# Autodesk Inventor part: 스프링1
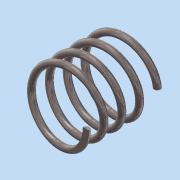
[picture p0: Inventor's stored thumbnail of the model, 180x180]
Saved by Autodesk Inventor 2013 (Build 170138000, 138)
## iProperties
Created: 2016-07
Part Number: 스프링1
Material: 스테인리스강
Document SubType Name: Modeling
Designer: Administrator
Density: 8.08 g/cm^3
Mass: 6.33594 g
Surface Area: 15.8123 cm^2
Volume: 0.784151 cm^3
Author: Administrator
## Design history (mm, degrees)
sketch "스케치1"
  geometry: L1 (0, 0)-(0, 22.5); L2 (0, 22.5)-(11.971, 22.5); C1 r 1 at (10, 0)
  constraints: 4 end point, 1 centre point, 1 horizontal alignment, 1 perpendicular, 1 vertical
  dimensions: "d0" = 22.5 distance of L1.start L1.end (derived); "d1" = 2 diameter of C1; "d2" = 20 diameter of C1.centre L1
feature "코일1" sketch "스케치1" pitch "d3" = 10; turns "d5" = 4; dims "d4" = 22.5 (= d0), "d6" = 0, angle "d7" = 90 deg, angle "d8" = 90 deg, "d9" = 0, "d10" = 0
sketch "스케치2"
  geometry: L1 (25, 15)-(0, 15); L2 (0, 15)-(0, -15); L3 (0, -15)-(25, -15); L4 (25, -15)-(25, 15); 2 further points
  constraints: 8 end point, 2 parallel, 1 coincident, 1 horizontal, 1 midpoint, 1 perpendicular
  dimensions: "d11" = 30 distance between parallel lines of L3 L1; "d13" = 25 distance of L1.start L1.end (derived)
extrude "돌출1" sketch "스케치2" stored distance "d14" = 30; taper "d15" = 0 deg
node "솔리드1"
